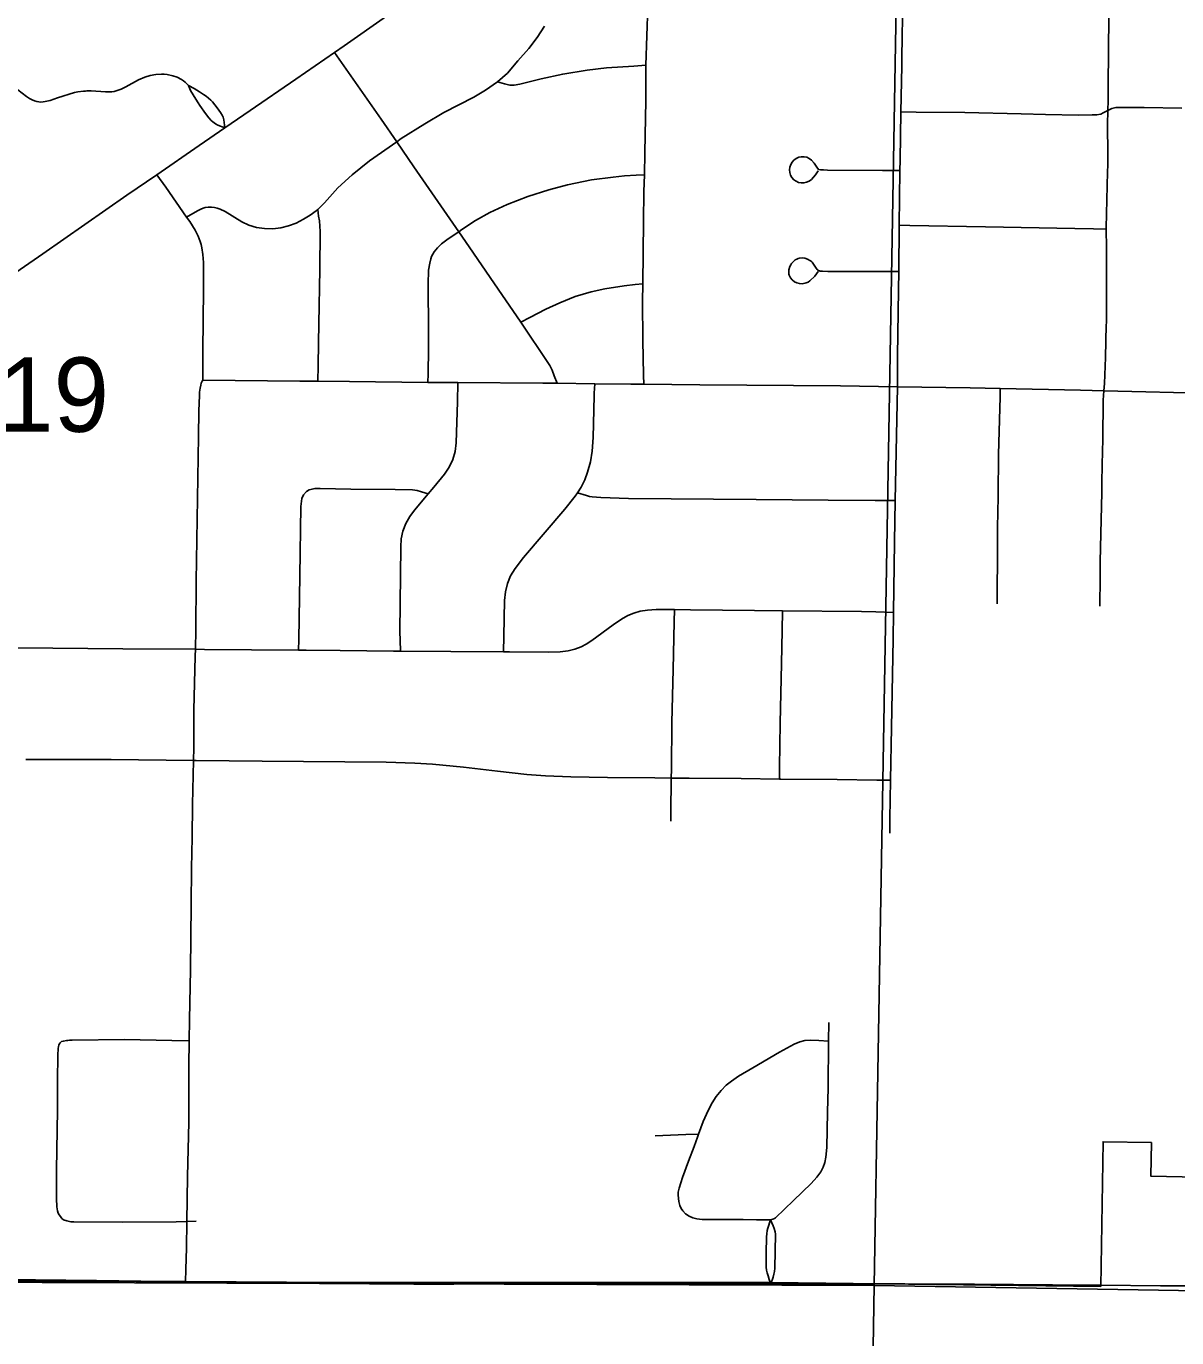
# Model space of a CAD drawing. Extents: x 0 to 34, y 0 to 22.
# Drawn here: x 7.145 to 7.793, y 18.41 to 19.148 of the extents above; entities that cross this region are included whole.
import ezdxf

# ---------------------------------------------------------------- set-up
doc = ezdxf.new("R2010")
doc.units = 0
for name, color, linetype in [('GM_X_City_Street', 7, 'Continuous'), ('GM_X_County_Road', 7, 'Continuous'), ('GM_X_Section', 7, 'Continuous'), ('GM_X_Section_Text', 7, 'Continuous'), ('GM_X_Township_Road', 7, 'Continuous'), ('GM_X_US_Route', 7, 'Continuous')]:
    doc.layers.add(name, color=color, linetype=linetype)

msp = doc.modelspace()

# ---------------------------------------------------------------- linework, layer by layer
at = {"layer": 'GM_X_City_Street'}
for points in [[(7.74948, 18.82203), (7.74961, 18.83818), (7.74956, 18.84192), (7.7496, 18.84558), (7.74962, 18.84683), (7.74986, 18.8629), (7.7506, 18.88586), (7.75054, 18.89081), (7.7505, 18.89309), (7.75054, 18.89613), (7.75065, 18.89679), (7.75077, 18.90171), (7.75114, 18.91587), (7.7512, 18.93791), (7.75165, 18.94313), (7.75201, 18.94729), (7.75249, 18.96193), (7.75299, 18.98024), (7.75309, 18.98144), (7.75311, 18.99327), (7.7531, 19.01937), (7.75308, 19.0237), (7.75298, 19.03411), (7.75297, 19.03482), (7.75374, 19.06643), (7.75398, 19.0701), (7.75393, 19.07265), (7.75384, 19.08003), (7.75383, 19.08248), (7.75371, 19.08681), (7.7537, 19.09298), (7.75394, 19.10097), (7.75398, 19.1025), (7.75405, 19.10476), (7.75399, 19.11535), (7.75428, 19.13398), (7.75424, 19.13891), (7.75425, 19.14072), (7.75436, 19.14754), (7.75438, 19.1699)], [(7.49266, 18.94681), (7.49254, 18.95198), (7.49211, 18.97159), (7.49198, 18.99335), (7.49209, 19.0034), (7.49246, 19.03838), (7.49276, 19.05532), (7.49302, 19.06479), (7.49335, 19.07706), (7.49376, 19.1066), (7.49387, 19.12527), (7.4939, 19.12633), (7.49494, 19.15946)], [(7.23535, 19.04091), (7.24147, 19.04445), (7.24328, 19.04545), (7.24472, 19.04603), (7.24577, 19.04624), (7.24751, 19.04642), (7.24936, 19.04645), (7.25104, 19.04632), (7.25255, 19.04599), (7.25417, 19.04547), (7.25712, 19.04408), (7.26637, 19.03828), (7.27044, 19.03631), (7.27479, 19.03508), (7.27929, 19.03444), (7.28384, 19.03438), (7.28836, 19.03487), (7.29277, 19.03597), (7.29703, 19.03759), (7.30106, 19.03972), (7.30497, 19.04204), (7.30835, 19.04444), (7.30915, 19.04521), (7.31299, 19.04895), (7.32046, 19.05733), (7.32861, 19.06464), (7.33835, 19.0725), (7.35361, 19.08325), (7.35622, 19.08509), (7.36939, 19.09347), (7.38023, 19.0997), (7.39699, 19.10834), (7.40362, 19.11232), (7.41031, 19.11699), (7.41594, 19.12188), (7.42184, 19.12877), (7.42795, 19.13576), (7.43263, 19.1419), (7.43683, 19.14837)], [(7.44385, 18.94741), (7.44232, 18.95157), (7.44117, 18.95468), (7.43981, 18.95735), (7.43603, 18.96304), (7.42652, 18.97721), (7.42345, 18.98171), (7.41077, 19.00031), (7.39241, 19.02711), (7.38855, 19.03268), (7.36329, 19.06915), (7.35361, 19.08325), (7.34481, 19.09605), (7.32522, 19.12409), (7.3186, 19.13357)], [(7.41031, 19.11699), (7.41435, 19.11597), (7.41727, 19.11525), (7.41979, 19.11518), (7.4229, 19.11565), (7.43501, 19.11865), (7.44712, 19.12137), (7.46089, 19.12362), (7.47167, 19.12486), (7.48716, 19.12588), (7.4939, 19.12633)], [(7.1404, 19.11253), (7.1453, 19.10877), (7.14701, 19.10766), (7.14842, 19.10697), (7.14982, 19.10635), (7.15109, 19.10596), (7.15227, 19.10575), (7.15338, 19.10568), (7.15454, 19.10575), (7.15569, 19.10588), (7.15857, 19.10654), (7.16262, 19.10797), (7.1722, 19.11095), (7.17407, 19.11138), (7.17725, 19.11179), (7.17852, 19.11182), (7.17916, 19.11196), (7.18042, 19.11189), (7.18171, 19.11195), (7.18978, 19.11141), (7.19196, 19.11134), (7.19316, 19.1114), (7.19459, 19.11164), (7.19567, 19.11192), (7.19846, 19.11286), (7.20118, 19.1142), (7.20829, 19.11814), (7.21179, 19.11968), (7.21486, 19.12063), (7.21804, 19.1212), (7.22127, 19.12135), (7.22279, 19.12129), (7.22448, 19.12109), (7.22765, 19.12044), (7.23011, 19.11958), (7.23246, 19.1184), (7.23356, 19.11765), (7.23459, 19.11682), (7.2364, 19.11489)], [(7.2364, 19.11489), (7.23764, 19.11211), (7.23901, 19.1097), (7.2405, 19.10722), (7.24184, 19.10521), (7.24285, 19.10373), (7.24602, 19.09927), (7.2478, 19.09681), (7.24912, 19.09537), (7.25007, 19.09447), (7.25169, 19.0934), (7.25294, 19.09274), (7.25683, 19.09113)], [(7.2364, 19.11489), (7.23966, 19.11323), (7.24259, 19.1115), (7.2448, 19.10995), (7.2463, 19.10893), (7.24761, 19.10792), (7.24893, 19.10673), (7.24997, 19.10573), (7.25258, 19.10238), (7.25446, 19.09971), (7.25539, 19.09824), (7.25587, 19.09723), (7.25629, 19.09567), (7.25665, 19.09262), (7.25683, 19.09113)], [(7.63742, 19.10012), (7.64609, 19.10002), (7.67344, 19.09971), (7.70511, 19.09901), (7.71874, 19.09871), (7.73741, 19.09832), (7.74498, 19.09839), (7.74757, 19.09839), (7.74987, 19.0988), (7.75128, 19.09964), (7.75394, 19.10097), (7.75623, 19.10211), (7.75838, 19.10255), (7.76208, 19.10268), (7.77438, 19.10256), (7.79552, 19.10227)], [(7.59083, 19.06698), (7.58943, 19.06467), (7.58701, 19.06214), (7.58576, 19.06122), (7.58437, 19.06055), (7.58287, 19.06019), (7.58133, 19.06017), (7.57981, 19.06046), (7.57838, 19.06107), (7.57712, 19.06196), (7.57609, 19.06313), (7.57531, 19.06447), (7.57483, 19.06594), (7.57468, 19.06748), (7.57487, 19.06901), (7.57537, 19.07047), (7.57617, 19.0718), (7.57724, 19.07294), (7.5785, 19.07387), (7.5799, 19.07455), (7.58141, 19.07492), (7.58294, 19.07492), (7.58441, 19.07457), (7.58579, 19.07391), (7.58701, 19.07295), (7.58867, 19.07128), (7.59009, 19.06907), (7.59103, 19.06779), (7.59224, 19.06759), (7.59386, 19.06752), (7.59608, 19.06739), (7.62699, 19.06722), (7.63685, 19.06713)], [(7.37123, 18.94789), (7.37133, 18.95276), (7.37141, 18.9567), (7.37157, 18.96287), (7.37154, 18.97075), (7.37146, 18.98467), (7.3714, 18.99532), (7.37125, 19.00309), (7.37156, 19.01109), (7.37218, 19.01506), (7.37277, 19.0174), (7.37326, 19.01869), (7.37469, 19.02128), (7.37658, 19.0237), (7.3788, 19.02586), (7.38257, 19.02859), (7.38855, 19.03268), (7.39027, 19.03385), (7.39789, 19.03898), (7.40598, 19.04355), (7.41586, 19.04807), (7.42748, 19.05252), (7.43922, 19.05635), (7.44966, 19.05909), (7.46335, 19.06193), (7.47538, 19.06347), (7.48187, 19.06422), (7.48845, 19.06456), (7.49302, 19.06479)], [(7.30922, 18.94854), (7.30936, 18.95712), (7.30957, 18.97021), (7.30977, 18.98084), (7.31042, 19.01162), (7.31056, 19.03287), (7.31008, 19.03873), (7.30968, 19.04151), (7.30915, 19.04521)], [(7.63647, 19.03635), (7.64244, 19.03623), (7.68505, 19.03536), (7.73531, 19.03452), (7.74584, 19.03428), (7.75298, 19.03411)], [(7.59085, 19.01022), (7.58996, 19.00897), (7.58891, 19.00758), (7.58614, 19.00505), (7.58515, 19.00436), (7.5841, 19.00385), (7.58338, 19.00367), (7.58187, 19.0034), (7.58032, 19.00346), (7.57883, 19.00385), (7.57745, 19.00456), (7.57625, 19.00554), (7.57528, 19.00676), (7.57481, 19.00748), (7.57458, 19.00815), (7.57437, 19.00886), (7.57425, 19.00965), (7.57435, 19.01117), (7.57485, 19.01306), (7.5754, 19.01413), (7.5759, 19.01482), (7.57655, 19.01557), (7.57706, 19.01607), (7.57798, 19.01681), (7.57885, 19.01732), (7.57957, 19.01765), (7.58031, 19.01785), (7.58185, 19.01796), (7.58339, 19.01776), (7.58487, 19.01731), (7.58622, 19.01656), (7.58682, 19.01618), (7.5874, 19.01556), (7.58817, 19.01449), (7.58891, 19.01329), (7.58966, 19.01225), (7.5902, 19.01151), (7.5907, 19.01101), (7.59194, 19.01051), (7.59327, 19.01046), (7.59636, 19.01036), (7.62588, 19.01029), (7.63616, 19.01026)], [(7.42345, 18.98171), (7.42852, 18.98439), (7.43757, 18.98917), (7.44536, 18.99262), (7.45411, 18.99614), (7.46313, 18.99888), (7.47079, 19.0006), (7.48164, 19.00223), (7.48786, 19.00293), (7.49209, 19.0034)], [(7.23477, 18.44162), (7.23496, 18.44881), (7.23525, 18.46064), (7.23545, 18.47566), (7.23581, 18.50104), (7.23653, 18.53149), (7.23668, 18.56322), (7.23686, 18.5774), (7.237, 18.58931), (7.23747, 18.61728), (7.238, 18.65396), (7.2382, 18.67446), (7.23843, 18.69186), (7.2387, 18.71038), (7.23921, 18.73515), (7.23936, 18.74221), (7.23939, 18.76335), (7.24026, 18.79378), (7.24033, 18.79768), (7.24053, 18.80872), (7.24082, 18.83607), (7.24196, 18.91753), (7.24223, 18.93187), (7.2426, 18.9406), (7.2427, 18.94234), (7.24298, 18.94469), (7.24331, 18.94638), (7.24364, 18.94745), (7.24408, 18.94849), (7.24456, 18.94916)], [(7.35571, 18.79668), (7.35551, 18.80285), (7.35537, 18.80746), (7.35588, 18.85535), (7.35616, 18.85985), (7.35715, 18.86421), (7.35875, 18.86844), (7.36093, 18.87235), (7.36362, 18.87603), (7.37136, 18.88514), (7.3746, 18.88896), (7.38047, 18.89623), (7.38308, 18.9002), (7.38513, 18.9045), (7.38652, 18.90908), (7.38715, 18.9138), (7.38776, 18.937), (7.38803, 18.94777)], [(7.41381, 18.79619), (7.41395, 18.805), (7.41429, 18.82522), (7.41479, 18.82996), (7.4159, 18.83463), (7.41776, 18.83907), (7.42026, 18.84315), (7.42503, 18.84939), (7.44828, 18.87658), (7.45408, 18.88382), (7.45537, 18.88579), (7.45743, 18.88893), (7.45947, 18.893), (7.46108, 18.89728), (7.46264, 18.9032), (7.46366, 18.90924), (7.46414, 18.91692), (7.46471, 18.94026), (7.46479, 18.94183), (7.46507, 18.94714)], [(7.63112, 18.69426), (7.63121, 18.70219), (7.63158, 18.72395), (7.6321, 18.7536), (7.63303, 18.80347), (7.63324, 18.81846), (7.63379, 18.85802), (7.63422, 18.88136), (7.63541, 18.94544)], [(7.69164, 18.82325), (7.69164, 18.82812), (7.69161, 18.83246), (7.69174, 18.84734), (7.69188, 18.86593), (7.69199, 18.87521), (7.6921, 18.8832), (7.69216, 18.88627), (7.69213, 18.88804), (7.69216, 18.89232), (7.69231, 18.89915), (7.69244, 18.90722), (7.69256, 18.91392), (7.6932, 18.93984), (7.69332, 18.9444)], [(7.29842, 18.79725), (7.2985, 18.80316), (7.29901, 18.8391), (7.29965, 18.8781), (7.30016, 18.88254), (7.30117, 18.88456), (7.30281, 18.88654), (7.30429, 18.88745), (7.30594, 18.88786), (7.30756, 18.88809), (7.31058, 18.88822), (7.32772, 18.88771), (7.35274, 18.88762), (7.36251, 18.88735), (7.36506, 18.88703), (7.36752, 18.88629), (7.37136, 18.88514)], [(7.45537, 18.88579), (7.46048, 18.88421), (7.46207, 18.88372), (7.46368, 18.88343), (7.46842, 18.88302), (7.48407, 18.88261), (7.55586, 18.88202), (7.59645, 18.88161), (7.62296, 18.88144), (7.63422, 18.88136)], [(7.14031, 18.79843), (7.19938, 18.79786), (7.24033, 18.79768), (7.2454, 18.79766), (7.29842, 18.79725), (7.3026, 18.79722), (7.32188, 18.79697), (7.35173, 18.79672), (7.35571, 18.79668), (7.38407, 18.79638), (7.41381, 18.79619), (7.41702, 18.79617), (7.4388, 18.79609), (7.44571, 18.7963), (7.45012, 18.79686), (7.45385, 18.79776), (7.45746, 18.79907), (7.46031, 18.80052), (7.4635, 18.80259), (7.47551, 18.81151), (7.48006, 18.81464), (7.48378, 18.81667), (7.48714, 18.81804), (7.49062, 18.81906), (7.49481, 18.81975), (7.49968, 18.8201), (7.5071, 18.82005), (7.50995, 18.82002), (7.51891, 18.81995), (7.55499, 18.81954), (7.57086, 18.8194), (7.6153, 18.819), (7.62335, 18.81876), (7.63324, 18.81846)], [(7.508, 18.70103), (7.50799, 18.70538), (7.50817, 18.72523), (7.50821, 18.7303), (7.50856, 18.75644), (7.5092, 18.78632), (7.5098, 18.81309), (7.50995, 18.82002)], [(7.56902, 18.72469), (7.5691, 18.73141), (7.56941, 18.75619), (7.57023, 18.78963), (7.57063, 18.80821), (7.57086, 18.8194)], [(7.14492, 18.7357), (7.1928, 18.73565), (7.23921, 18.73515), (7.24068, 18.73514), (7.27798, 18.73473), (7.34763, 18.73413), (7.36381, 18.73361), (7.37377, 18.73307), (7.39112, 18.73131), (7.41027, 18.72904), (7.42693, 18.72726), (7.43744, 18.7265), (7.4517, 18.72595), (7.47219, 18.72563), (7.49891, 18.72529), (7.50817, 18.72523), (7.51819, 18.72517), (7.54742, 18.72488), (7.56902, 18.72469), (7.56979, 18.72468), (7.60151, 18.72435), (7.6239, 18.72405), (7.63158, 18.72395)], [(7.56397, 18.47658), (7.56536, 18.47697), (7.56626, 18.47735), (7.56691, 18.47775), (7.57704, 18.48756), (7.58684, 18.49704), (7.59013, 18.50066), (7.59229, 18.50358), (7.59372, 18.50617), (7.59468, 18.50894), (7.59523, 18.51187), (7.59565, 18.51737), (7.59616, 18.53724), (7.59643, 18.5509), (7.59673, 18.57722), (7.59685, 18.58758)], [(7.16488, 18.57689), (7.16606, 18.57723), (7.16767, 18.57752), (7.16858, 18.57762), (7.16938, 18.57766), (7.17088, 18.57776), (7.20037, 18.57812), (7.22702, 18.57759), (7.23686, 18.5774)], [(7.16613, 18.47663), (7.16513, 18.47743), (7.16429, 18.47842), (7.16364, 18.47937), (7.16312, 18.48037), (7.16267, 18.48169), (7.16229, 18.48393), (7.16203, 18.48865), (7.16209, 18.50483), (7.16268, 18.53832), (7.16265, 18.55505), (7.16278, 18.56935), (7.16299, 18.57311), (7.16317, 18.57419), (7.16338, 18.57483), (7.16366, 18.57542), (7.16426, 18.57622), (7.16488, 18.57689)], [(7.56397, 18.47658), (7.5561, 18.47662), (7.54858, 18.4767), (7.53424, 18.47683), (7.52556, 18.47686), (7.52258, 18.47719), (7.52029, 18.47778), (7.51817, 18.47872), (7.51626, 18.48002), (7.51464, 18.48165), (7.51369, 18.48306), (7.51299, 18.48462), (7.5124, 18.48692), (7.51198, 18.49045), (7.51207, 18.49217), (7.51256, 18.49451), (7.51439, 18.50038), (7.51793, 18.50967), (7.52107, 18.51786), (7.52296, 18.52322), (7.52355, 18.52485), (7.5261, 18.53196), (7.52886, 18.53816), (7.53115, 18.54249), (7.53349, 18.54605), (7.53616, 18.54938), (7.53915, 18.5524), (7.54197, 18.5547), (7.54605, 18.55742), (7.55408, 18.5621), (7.56916, 18.57093), (7.57726, 18.5754), (7.58057, 18.57682), (7.58339, 18.57753), (7.58637, 18.57772), (7.59124, 18.57749), (7.59673, 18.57722)], [(7.49918, 18.52394), (7.51629, 18.52458), (7.52355, 18.52485)], [(7.16613, 18.47663), (7.16801, 18.47599), (7.17015, 18.47555), (7.17188, 18.47542), (7.19916, 18.47537), (7.22955, 18.47545), (7.23545, 18.47566), (7.24072, 18.47584)], [(7.56426, 18.44064), (7.56329, 18.4431), (7.56267, 18.44503), (7.56208, 18.44681), (7.5617, 18.44832), (7.56152, 18.45006), (7.56164, 18.45777), (7.56176, 18.46701), (7.56186, 18.46879), (7.56212, 18.47061), (7.56242, 18.47199), (7.56397, 18.47658)], [(7.56426, 18.44064), (7.56545, 18.44438), (7.56591, 18.44608), (7.56623, 18.44751), (7.56642, 18.44948), (7.56683, 18.46862), (7.56666, 18.46992), (7.56614, 18.47169), (7.56557, 18.47316), (7.56397, 18.47658)]]:
    msp.add_lwpolyline(points, dxfattribs=at)
at = {"layer": 'GM_X_County_Road'}
for p, q in [((7.63797, 19.13076), (7.63909, 19.1987)), ((7.63647, 19.03635), (7.63685, 19.06713)), ((7.63616, 19.01026), (7.63647, 19.03635)), ((7.44385, 18.94741), (7.46507, 18.94714))]:
    msp.add_line(p, q, dxfattribs=at)
for points in [[(7.3186, 19.13357), (7.32408, 19.13734), (7.34789, 19.15405), (7.36107, 19.16309)], [(7.25683, 19.09113), (7.27114, 19.10093), (7.29675, 19.11855), (7.3186, 19.13357)], [(7.63742, 19.10012), (7.63789, 19.12577), (7.63797, 19.13076)], [(7.63685, 19.06713), (7.63693, 19.07297), (7.63742, 19.10012)], [(7.21864, 19.06479), (7.24237, 19.08123), (7.25683, 19.09113)], [(7.09828, 18.98171), (7.10672, 18.98754), (7.13134, 19.00434), (7.15434, 19.02016), (7.20178, 19.05322), (7.21864, 19.06479)], [(7.21864, 19.06479), (7.22361, 19.05782), (7.23535, 19.04091)], [(7.23535, 19.04091), (7.23708, 19.03842), (7.24009, 19.03363), (7.24181, 19.03024), (7.24297, 19.02727), (7.24358, 19.02551), (7.24397, 19.02358), (7.24456, 19.0198), (7.24479, 19.01538), (7.2448, 18.99734), (7.24465, 18.98553), (7.24448, 18.96283), (7.24456, 18.94916)], [(7.63541, 18.94544), (7.63545, 18.95492), (7.63548, 18.96268), (7.63602, 18.99995), (7.63616, 19.01026)], [(7.24456, 18.94916), (7.29915, 18.94863), (7.30922, 18.94854)], [(7.30922, 18.94854), (7.32711, 18.94838), (7.37123, 18.94789)], [(7.37123, 18.94789), (7.37678, 18.94783), (7.38803, 18.94777)], [(7.38803, 18.94777), (7.43579, 18.94752), (7.44385, 18.94741)], [(7.46507, 18.94714), (7.48547, 18.94687), (7.49266, 18.94681)], [(7.49266, 18.94681), (7.52428, 18.94653), (7.60346, 18.94597), (7.63541, 18.94544)], [(7.63541, 18.94544), (7.67642, 18.94476), (7.69332, 18.9444)], [(7.69332, 18.9444), (7.73852, 18.94344), (7.75165, 18.94313)], [(7.75165, 18.94313), (7.81458, 18.94161), (7.81747, 18.94153)]]:
    msp.add_lwpolyline(points, dxfattribs=at)
at = {"layer": 'GM_X_Section'}
for points in [[(6.69788, 19.47262), (7.63985, 19.45485), (7.62229, 18.4397), (6.68531, 18.44295), (6.6975, 19.43966)], [(7.63985, 19.45485), (8.64101, 19.4232), (8.63932, 18.42286), (7.62229, 18.4397)], [(6.68531, 18.44295), (7.62229, 18.4397), (7.606, 17.42984), (6.66543, 17.44151)], [(7.62229, 18.4397), (8.63932, 18.42286), (8.6173, 17.41124), (7.606, 17.42984)]]:
    msp.add_lwpolyline(points, close=True, dxfattribs=at)
at = {"layer": 'GM_X_Township_Road'}
for points in [[(6.78956, 18.44837), (6.81244, 18.44825), (6.83779, 18.4477), (6.86924, 18.44731), (6.89091, 18.44704), (6.90436, 18.44674), (6.92486, 18.4463), (6.96278, 18.44561), (6.99509, 18.44504), (7.03488, 18.44433), (7.07715, 18.44373), (7.1132, 18.44322), (7.13309, 18.44301), (7.18469, 18.44253), (7.23477, 18.44162)], [(7.23477, 18.44162), (7.23564, 18.4416), (7.26363, 18.4413), (7.28849, 18.44105), (7.32018, 18.44069), (7.33825, 18.4406), (7.36332, 18.44048), (7.38584, 18.44036), (7.42958, 18.44056), (7.48304, 18.44061), (7.49361, 18.44074), (7.50666, 18.44069), (7.52468, 18.44066), (7.55079, 18.44062), (7.56426, 18.44064)], [(7.56426, 18.44064), (7.57814, 18.44066), (7.59927, 18.44057), (7.63968, 18.44052), (7.67884, 18.44038), (7.72268, 18.44006), (7.75002, 18.4398)], [(7.75002, 18.4398), (7.78359, 18.43954), (7.81124, 18.43944)]]:
    msp.add_lwpolyline(points, dxfattribs=at)
at = {"layer": 'GM_X_US_Route'}
msp.add_lwpolyline([(7.12661, 18.44206), (7.15999, 18.442), (7.20672, 18.44193), (7.23468, 18.44189), (7.32011, 18.44141), (7.52461, 18.44137), (7.56418, 18.44136), (7.74992, 18.43911), (7.7512, 18.52059), (7.77844, 18.5201), (7.77816, 18.50116), (7.80447, 18.50068), (7.81168, 18.50055), (7.81176, 18.50694), (7.8454, 18.50633), (7.84447, 18.43742), (7.81501, 18.43795), (7.81443, 18.38394)], dxfattribs=at)

# ---------------------------------------------------------------- texts
at = {"layer": 'GM_X_Section_Text'}
msp.add_text('19', height=0.041856, rotation=0.00001, dxfattribs=at).set_placement((7.1294, 18.92008))

doc.saveas('drawing.dxf')
